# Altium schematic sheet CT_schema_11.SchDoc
size 278 x 170 mm
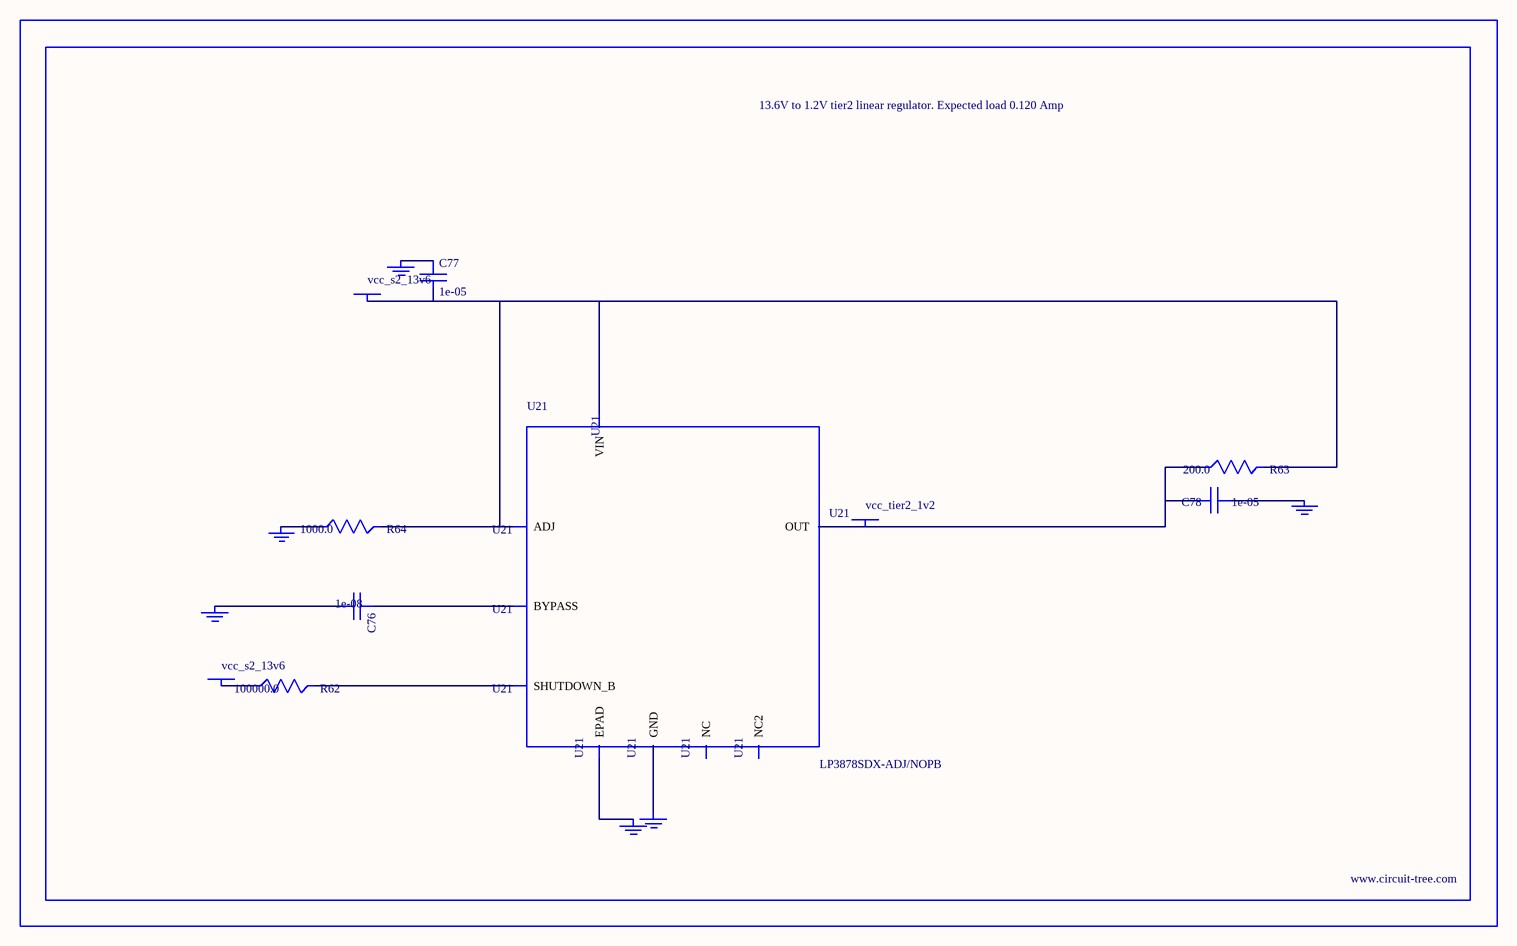
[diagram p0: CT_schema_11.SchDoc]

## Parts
BORDER10  (no value)
C76  1e-08  [C0402]
C77  1e-05  [C1210]
C78  1e-05  [C0805]
GND_INSTANCE_10_0  (no value)
GND_INSTANCE_10_1  (no value)
GND_INSTANCE_10_2  (no value)
GND_INSTANCE_10_3  (no value)
GND_INSTANCE_10_4  (no value)
GND_INSTANCE_10_5  (no value)
POWER_INSTANCE_10_0  vcc_s2_13v6
POWER_INSTANCE_10_1  vcc_s2_13v6
POWER_INSTANCE_10_2  vcc_tier2_1v2
R62  100000.0  [R0603]
R63  200.0  [R0603]
R64  1000.0  [R0603]
U21  LP3878SDX-ADJ/NOPB  [WSON-8]

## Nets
NetC76_1: C76.1 U21.1(BYPASS)
NetC76_2: C76.2 GND_INSTANCE_10_0.0(GND)
NetC77_1: C77.1 GND_INSTANCE_10_1.0(GND)
NetC77_2: C77.2 POWER_INSTANCE_10_0.0(PWR) R63.2 R64.2 U21.4(VIN) U21.6(ADJ)
NetC78_1: C78.1 GND_INSTANCE_10_2.0(GND)
NetC78_2: C78.2 POWER_INSTANCE_10_2.0(PWR) R63.1 U21.5(OUT)
NetGND_INSTANCE_10_3_0: GND_INSTANCE_10_3.0(GND) R64.1
NetGND_INSTANCE_10_4_0: GND_INSTANCE_10_4.0(GND) U21.PAD(EPAD)
NetGND_INSTANCE_10_5_0: GND_INSTANCE_10_5.0(GND) U21.3(GND)
NetPOWER_INSTANCE_10_1_0: POWER_INSTANCE_10_1.0(PWR) R62.1
NetR62_2: R62.2 U21.8(SHUTDOWN_B)

Not connected (* = marked no-connect by the designer): U21 2(NC) 7(NC2)

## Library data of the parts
BORDER10 = BORDER_PAGE10
C76 = C0402C103K3RAC
C77 = C1210C106K5PACTU
C78 = GRM219R60J106ME19D
GND_INSTANCE_10_0-GND_INSTANCE_10_5 = GND
POWER_INSTANCE_10_0-POWER_INSTANCE_10_2 = PWR
R62 = RC0603JR-07100KL
R63 = RC0603JR-07200RL
R64 = RC0603JR-071KL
